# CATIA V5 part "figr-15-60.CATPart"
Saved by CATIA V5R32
Part number: Part1
Bounding box of the stored display mesh (mm): x -35.944 to 35.944, y -33.497 to 33.497, z 0 to 50.428
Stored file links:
  D:\PROJECTS\Project 2022\CATIA V5 6R 2022\Resources\Part Files\c15_catia_v5_6r2022_prt\figr-15-60.CATPart
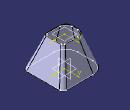
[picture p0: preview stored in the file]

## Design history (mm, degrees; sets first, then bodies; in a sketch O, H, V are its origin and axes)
SheetMetalParameters1: Thickness 1, BendRadius 2, KFactor 0.400515 {= log(min(100,max(20*SheetMetalParameters1.BendRadius,SheetMetalParameters1.Thickness)/SheetMetalParameters1.Thickness))/log(100)/2}, ReliefRadialLength 1, ReliefAxialLength 2, MinimumBendRadius 0
Body1 (main body)
  Sketch1 on xy-plane, origin (0, 0, 0), H (1, 0, 0), V (0, 1, 0)
    line L1 (-15, -32.5532) -> (30, -32.5532)
    line L2 (35, -27.5532) -> (35, 27.5532)
    line L3 (30, 32.5532) -> (-15, 32.5532)
    line L4 (-35, 12.5532) -> (-35, -12.5532)
    arc A1 centre (-15, -12.5532) radius 20 from (-35, -12.5532) to (-15, -32.5532) ccw
    arc A2 centre (-15, 12.5532) radius 20 from (-35, 12.5532) to (-15, 32.5532) cw
    arc A3 centre (30, -27.5532) radius 5 from (30, -32.5532) to (35, -27.5532) ccw
    arc A4 centre (30, 27.5532) radius 5 from (35, 27.5532) to (30, 32.5532) ccw
    radius A1 = 20
    radius A2 = 20
    radius A3 = 5
    radius A4 = 5
    distance L2 L4 = 70
    horizontal: L1 H, L3 H
    vertical: L2 V, L4 V
    tangency: A1 L4, A1 L1, A2 L4, A2 L3, A3 L1, A3 L2, A4 L2, A4 L3
    symmetry: L3 L1 H, L4 L2 V
  Plane1: type Offset, RefPlane xy-plane, Offset 50
  Sketch2 "Sketch.2" on Plane1, origin (0, 0, 50), H (1, 0, 0), V (0, 1, 0)
    line L1 (-7.5, 15) -> (14.5, 15)
    line L2 (17.5, 12) -> (17.5, -12)
    line L3 (14.5, -15) -> (-7.5, -15)
    line L4 (-17.5, -5) -> (-17.5, 5)
    arc A1 centre (-7.5, -5) radius 10 from (-7.5, -15) to (-17.5, -5) cw
    arc A2 centre (-7.5, 5) radius 10 from (-17.5, 5) to (-7.5, 15) cw
    arc A3 centre (14.5, 12) radius 3 from (14.5, 15) to (17.5, 12) cw
    arc A4 centre (14.5, -12) radius 3 from (17.5, -12) to (14.5, -15) cw
    radius A1 = 10
    radius A2 = 10
    radius A3 = 3
    radius A4 = 3
    distance L4 L2 = 35
    distance L1 L3 = 30
    horizontal: L1 H, L3 H
    vertical: L2 V, L4 V
    tangency: A1 L3, A1 L4, A2 L4, A2 L1, A3 L1, A3 L2, A4 L2, A4 L3
    symmetry: L4 L2 V, L1 L3 H
  Hopper1: KFacteur 0.400515 {= SheetMetalParameters1.KFactor}, HopperFixedSideType 0, HopperType 0, Hopper_InvariantPoint vertex [element of Sketch1 | element of Sketch1], Hopper_NeutralFiber 0, Hopper_ReferenceEdge edge [face of Hopper1 | face of Hopper1], Hopper_Surface {loft Sections (Sketch1; Sketch2), SectionCouplingPoints ({coupling CouplingPoints (vertex [element of Sketch1 | element of Sketch1]; vertex [element of Sketch2 | element of Sketch2])}; {coupling CouplingPoints (vertex [element of Sketch1 | element of Sketch1]; vertex [element of Sketch2 | element of Sketch2])}; {coupling CouplingPoints (vertex [element of Sketch1 | element of Sketch1]; vertex [element of Sketch2 | element of Sketch2])}; {coupling CouplingPoints (vertex [element of Sketch1 | element of Sketch1]; vertex [element of Sketch2 | element of Sketch2])}; {coupling CouplingPoints (vertex [element of Sketch1 | element of Sketch1]; vertex [element of Sketch2 | element of Sketch2])}; {coupling CouplingPoints (vertex [element of Sketch1 | element of Sketch1]; vertex [element of Sketch2 | element of Sketch2])}; {coupling CouplingPoints (vertex [element of Sketch1 | element of Sketch1]; vertex [element of Sketch2 | element of Sketch2])}; {coupling CouplingPoints (vertex [element of Sketch1 | element of Sketch1]; vertex [element of Sketch2 | element of Sketch2])})}, Hopper_TearWires edge [face of Hopper1 | face of Hopper1], Hopper_Thickness 1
